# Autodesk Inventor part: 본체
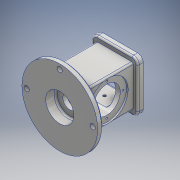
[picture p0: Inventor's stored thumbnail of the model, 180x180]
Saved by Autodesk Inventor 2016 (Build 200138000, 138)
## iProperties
Created: 2019-08
Part Number: 본체
Material: 알루미늄 6061
Document SubType Name: Modeling
Designer: 3sil_0101
Density: 2.7 g/cm^3
Appearance: 알루미늄 - 평지
Mass: 1016.75 g
Surface Area: 790.795 cm^2
Volume: 376.574 cm^3
Author: 3sil_0101
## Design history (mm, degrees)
sketch "스케치1"
  geometry: L1 (33, 37)-(-33, 37); L2 (-33, 37)-(-33, -37); L3 (-33, -37)-(33, -37); L4 (33, -37)-(33, 37); 2 further points
  constraints: 8 end point, 2 midpoint, 2 parallel, 1 horizontal, 1 perpendicular
  dimensions: "d0" = 74 distance of L3.end L1.start; "d1" = 66 distance of L2.end L3.end
extrude "돌출1" new body sketch "스케치1" stored distance "d4" = 88; taper "d5" = 0 deg
sketch "스케치7"
  geometry: L1 (-22, -22)-(22, -22); L2 (22, -22)-(22, 22); L3 (22, 22)-(-22, 22); L4 (-22, 22)-(-22, -22); 3 further points
  constraints: 8 end point, 2 midpoint, 2 parallel, 1 horizontal, 1 horizontal alignment, 1 perpendicular, 1 vertical alignment
  dimensions: "d44" = 44 distance of L3.end L2.end; "d45" = 44 distance of L2.end L1.end
extrude "돌출7" cut sketch "스케치7" distance "d48" = 72; taper "d49" = 0 deg
sketch "스케치2"
  geometry: C1 r 67.5 at (0, 0); C2 r 4.5 at (-59, 0); C3 r 4.5 at (0, 59); C4 r 4.5 at (59, 0); 1 further point
  constraints: 4 centre point, 1 coincident, 1 equal radius, 1 horizontal alignment
  dimensions: "d6" = 135 diameter of C1; "d7" = 9 diameter of C2; "d8" = 118 distance of C4.centre C2.centre; "d9" = 59 distance of point (0, 0) C2.centre; "d10" = 59 distance of point (0, 0) C3.centre
extrude "돌출2" join sketch "스케치2" distance "d12" = 10; taper "d13" = 0 deg
sketch "스케치3"
  geometry: L1 (-41, -46)-(41, -46); L2 (41, -46)-(41, 46); L3 (41, 46)-(-41, 46); L4 (-41, 46)-(-41, -46); L5 (-22, 22)-(-22, -22) reference; L6 (-22, -22)-(22, -22) reference; L7 (22, -22)-(22, 22) reference; L8 (22, 22)-(-22, 22) reference; L9 (-27.5, -27.5)-(27.5, -27.5); L10 (27.5, -27.5)-(27.5, 27.5); L11 (27.5, 27.5)-(-27.5, 27.5); L12 (-27.5, 27.5)-(-27.5, -27.5); 4 further points
  constraints: 16 end point, 4 midpoint, 4 parallel, 2 horizontal, 2 perpendicular, 1 horizontal alignment, 1 vertical alignment
  dimensions: "d14" = 92 distance of L3.end L1.start; "d15" = 82 distance of L2.end L3.end; "d20" = 55 distance of L11.end L10.end; "d21" = 55 distance of L10.end L9.end
extrude "돌출3" join sketch "스케치3" distance "d16" = 10; taper "d17" = 0 deg
fillet "모깎기1" dims "d18" = 10
fillet "모깎기2" dims "d19" = 3
sketch "스케치4"
  geometry: L1 (-33.5, -13)-(101.5, -13) reference; C1 r 24 at (34, 41); 1 further point
  constraints: 1 centre point
  dimensions: "d22" = 54 distance from line of C1.centre L1; "d23" = 48 diameter of C1
extrude "돌출4" cut sketch "스케치4" distance "d24" = 78; taper "d25" = 0 deg
sketch "스케치5"
  geometry: C1 r 35 at (34, 41); 1 further point
  constraints: 1 centre point, 1 coincident
  dimensions: "d26" = 70 diameter of C1
extrude "돌출5" cut sketch "스케치5" distance "d27" = 3; taper "d28" = 0 deg
sketch "스케치6"
  geometry: C1 r 35 at (-34, 41); 1 further point
  constraints: 1 centre point, 1 coincident
  dimensions: "d29" = 70 diameter of C1
extrude "돌출6" cut sketch "스케치6" distance "d30" = 3; taper "d31" = 0 deg
chamfer "모따기1" distance "d32" = 3; stored, may be unused: second distance "d33" = 2, angle "d34" = 45 deg
hole "구멍1" diameter "d37" = 25; stored, may be unused: countersink angle "d41" = 90 deg, drill point angle "d43" = 118 deg; dims "d38" = 6, "d39" = 50, "d40" = 18, "d42" = 8, "d46" = 10, "d47" = 10
fillet "모깎기3" dims "d50" = 3
sketch "스케치8"
  geometry: 1 further point
sketch "스케치9"
  geometry: 2 further points
  constraints: 1 vertical alignment
  dimensions: "d51" = 29 distance of point (0, 0) point (0, 29)
hole "구멍2" sketch "스케치9" at (0, 29) diameter "d52" = 3.242; stored, may be unused: countersink angle "d56" = 90 deg, drill point angle "d58" = 118 deg; dims "d53" = 4, "d54" = 50, "d55" = 18, "d57" = 6
sketch "스케치10"
  geometry: L1 (-41, 36)-(-41, -36) reference; L2 (-31, -46)-(31, -46) reference; 2 further points
  dimensions: "d62" = 10 distance from line of point (-31, -36) L1; "d63" = 10 distance from line of L2 point (-31, -36)
hole "구멍3" sketch "스케치10" at (-31, -36) diameter "d64" = 3.242; stored, may be unused: countersink angle "d68" = 90 deg, drill point angle "d70" = 118 deg; dims "d65" = 4, "d66" = 50, "d67" = 18, "d69" = 6
chamfer "모따기2" distance "d77" = 1; stored, may be unused: second distance "d78" = 2, angle "d79" = 45 deg
fillet "모깎기4" dims "d80" = 3
sketch "스케치11"
  geometry: 2 further points
  constraints: 1 other
sketch "스케치12"
  geometry: L1 (-37.5, -98)-(97.5, -98) reference; 3 further points
  constraints: 2 vertical alignment
  dimensions: "d82" = 43 distance of point (30, -61) point (30, -18); "d83" = 37 distance from line of L1 point (30, -61)
hole "구멍4" sketch "스케치12" at (30, -18), (30, -61) diameter "d84" = 4.917; stored, may be unused: countersink angle "d88" = 90 deg, drill point angle "d90" = 118 deg; dims "d85" = 27, "d86" = 50, "d87" = 18, "d89" = 32.1
feature "엠보싱1" dims "d0" = 74, "d1" = 66, "d91" = 0.5, "d92" = 0
sketch "스케치13"
  geometry: L1 (-27.5, 27.5)-(-27.5, -27.5) reference; L2 (-27.5, -27.5)-(27.5, -27.5) reference; L3 (27.5, -27.5)-(27.5, 27.5) reference; L4 (27.5, 27.5)-(-27.5, 27.5) reference; L5 (22, 19)-(22, -19) reference; L6 (19, -22)-(-19, -22) reference; L7 (-22, -19)-(-22, 19) reference; L8 (-19, 22)-(19, 22) reference; A1 r 3 centre (19, -19) between (19, -22) and (22, -19) reference; A2 r 3 centre (-19, -19) between (-22, -19) and (-19, -22) reference; A3 r 3 centre (-19, 19) between (-19, 22) and (-22, 19) reference; A4 r 3 centre (19, 19) between (22, 19) and (19, 22) reference; 1 further point
extrude "돌출8" join sketch "스케치13" distance "d93" = 2; taper "d94" = 0 deg
node "솔리드1"
pattern_circular "원형 패턴1" dims angle "d60" = 360 deg
mirror "대칭1"
pattern_linear "직사각형 패턴1" dims "d73" = 72, "d76" = 62
node "투영된 루프1"
node "투영된 루프2"
